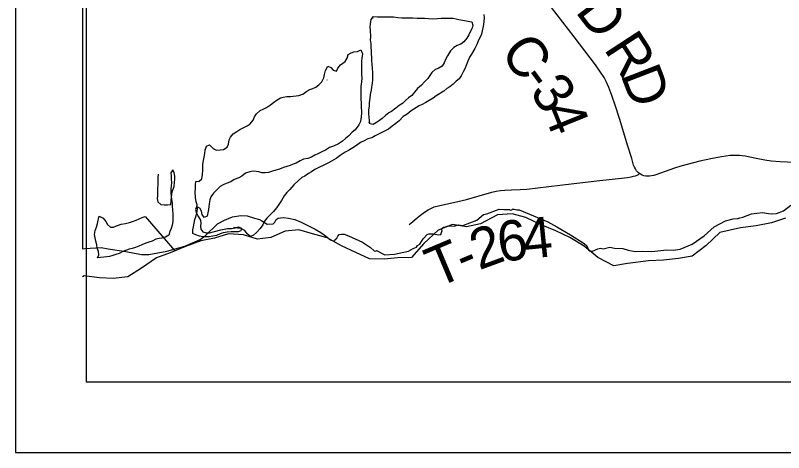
# Model space of a CAD drawing. Extents: x 63.4 to 97.4, y 0.4 to 22.4.
# Drawn here: x 65.412 to 66.497, y 14.42 to 15.037 of the extents above; entities that cross this region are included whole.
import ezdxf

# ---------------------------------------------------------------- set-up
doc = ezdxf.new("R2010")
doc.units = 0
for name, color, linetype in [('GM_X_County_Road', 7, 'Continuous'), ('GM_X_County_Road_Text', 7, 'Continuous'), ('GM_X_Major_Lake', 7, 'Continuous'), ('GM_X_Minor_River', 7, 'Continuous'), ('GM_X_Township_Road', 7, 'Continuous'), ('GM_X_Township_Road_Text', 7, 'Continuous'), ('SH_Cut_Line', 7, 'Continuous'), ('SH_Data', 7, 'Continuous')]:
    doc.layers.add(name, color=color, linetype=linetype)

msp = doc.modelspace()

# ---------------------------------------------------------------- linework, layer by layer
at = {"layer": 'GM_X_County_Road'}
for points in [[(65.5072, 16.9001), (65.5072, 14.7073), (65.5106, 14.7078), (65.5335, 14.7089), (65.5434, 14.707), (65.5685, 14.7035), (65.5904, 14.6991), (65.6006, 14.6993), (65.6261, 14.7038), (65.6518, 14.7108), (65.6733, 14.7202), (65.6803, 14.7255), (65.6978, 14.7425), (65.7075, 14.7478), (65.719, 14.7523), (65.7309, 14.7544), (65.7399, 14.7536), (65.75, 14.7507), (65.757, 14.7485), (65.7604, 14.7466), (65.7678, 14.7421), (65.7763, 14.7427), (65.7789, 14.7449), (65.7809, 14.7485), (65.7834, 14.7503), (65.7868, 14.751), (65.7909, 14.7514), (65.7983, 14.7507), (65.8072, 14.7484), (65.8161, 14.745), (65.8357, 14.7348), (65.8436, 14.7301), (65.8486, 14.7268), (65.8573, 14.7199), (65.8609, 14.7183), (65.8636, 14.7187), (65.8641, 14.7206), (65.8665, 14.7224), (65.868, 14.7253), (65.8698, 14.7276), (65.8731, 14.7281), (65.8767, 14.7279), (65.8828, 14.7257), (65.9027, 14.7164), (65.914, 14.7092), (65.919, 14.7046), (65.9214, 14.7039), (65.9223, 14.7048), (65.9343, 14.6988), (65.9476, 14.6996), (65.9675, 14.7038), (65.974, 14.7077), (65.9787, 14.7096), (65.9803, 14.7119), (65.9834, 14.7137), (65.9885, 14.7215), (65.9939, 14.7275), (65.9965, 14.7285), (66.0026, 14.7284), (66.0099, 14.727), (66.0133, 14.7274), (66.0151, 14.7329), (66.0141, 14.7339), (66.0152, 14.7364), (66.0169, 14.7377), (66.0187, 14.7379), (66.0222, 14.7391), (66.0267, 14.7396), (66.0319, 14.7393), (66.0384, 14.7409), (66.0445, 14.7402), (66.0643, 14.7479), (66.0733, 14.7555), (66.078, 14.7566), (66.0956, 14.7631), (66.1023, 14.7627), (66.1101, 14.7626), (66.1111, 14.7618), (66.1135, 14.7621), (66.114, 14.7632), (66.1168, 14.7633), (66.1204, 14.7623), (66.1239, 14.7624), (66.1643, 14.7451), (66.1769, 14.7383), (66.1965, 14.7272), (66.2157, 14.7149), (66.2194, 14.7115), (66.222, 14.706), (66.2243, 14.704), (66.2276, 14.7037), (66.2348, 14.7074), (66.2388, 14.7081), (66.2425, 14.707), (66.2519, 14.7095), (66.2587, 14.7081), (66.2703, 14.7078), (66.2779, 14.7055), (66.2879, 14.7033), (66.2978, 14.704), (66.3113, 14.7033), (66.3326, 14.7057), (66.3414, 14.7052), (66.3515, 14.7066), (66.3684, 14.7137), (66.3852, 14.7254), (66.3994, 14.7384), (66.4155, 14.7467), (66.4263, 14.7497), (66.4326, 14.7498), (66.4356, 14.7508), (66.4398, 14.7521), (66.4519, 14.7567), (66.4597, 14.7576), (66.4675, 14.7584), (66.476, 14.7573), (66.4809, 14.7565), (66.4872, 14.7572), (66.4972, 14.761), (66.5076, 14.7689)], [(66.2938, 14.8133), (66.2925, 14.8144), (66.2912, 14.8157), (66.2898, 14.8175), (66.2882, 14.8199), (66.2868, 14.8226), (66.2856, 14.8255), (66.2829, 14.8345), (66.2774, 14.8523), (66.2656, 14.8909), (66.2601, 14.9087), (66.255, 14.9234), (66.2505, 14.935), (66.2467, 14.9434), (66.2438, 14.9488), (66.2389, 14.9567), (66.2318, 14.9668), (66.2017, 15.0065), (66.1617, 15.058), (66.1446, 15.0801)], [(66.5236, 14.8284), (66.4925, 14.83), (66.48, 14.8311), (66.4708, 14.8323), (66.4585, 14.8348), (66.4433, 14.838), (66.4387, 14.8386), (66.4351, 14.8391), (66.4321, 14.8391), (66.4285, 14.8391), (66.422, 14.8387), (66.4097, 14.837), (66.3944, 14.8343), (66.3793, 14.831), (66.3523, 14.824), (66.3434, 14.8212), (66.317, 14.8118), (66.3139, 14.8109), (66.3108, 14.8103), (66.3079, 14.8099), (66.305, 14.8098), (66.3026, 14.8099), (66.3001, 14.8103), (66.2975, 14.8111), (66.2951, 14.8124), (66.2938, 14.8133)]]:
    msp.add_lwpolyline(points, dxfattribs=at)
at = {"layer": 'GM_X_Major_Lake'}
for points in [[(66.5001, 14.7507), (66.4804, 14.7439), (66.4588, 14.7397), (66.4367, 14.7367), (66.4071, 14.7302), (66.3882, 14.7119), (66.3684, 14.6971), (66.3491, 14.6937), (66.3278, 14.6914), (66.3066, 14.6903), (66.277, 14.6865), (66.2576, 14.6834), (66.2349, 14.6952), (66.2159, 14.7112), (66.1954, 14.7233), (66.1757, 14.7328), (66.1552, 14.7412), (66.1335, 14.7514), (66.1142, 14.7564), (66.0933, 14.7552), (66.0694, 14.7423), (66.0493, 14.7381), (66.0296, 14.7415)], [(66.0296, 14.7415), (66.0095, 14.7336), (65.9894, 14.7149), (65.9719, 14.6948), (65.9522, 14.6944), (65.9332, 14.6925), (65.9123, 14.6932), (65.8933, 14.702), (65.8729, 14.7115), (65.8527, 14.7229), (65.8322, 14.7282), (65.8125, 14.7339), (65.7932, 14.732), (65.773, 14.7233), (65.7541, 14.721), (65.7343, 14.7271), (65.7135, 14.7286), (65.6934, 14.7225), (65.6744, 14.7183), (65.6528, 14.7107), (65.6308, 14.7016), (65.6118, 14.6943), (65.5905, 14.6799), (65.5712, 14.6677), (65.5503, 14.6654), (65.531, 14.6662), (65.5093, 14.6689), (65.5072, 14.6675)]]:
    msp.add_lwpolyline(points, dxfattribs=at)
at = {"layer": 'GM_X_Minor_River'}
for points in [[(65.9128, 14.8838), (65.912, 14.8929), (65.9116, 14.8978), (65.9116, 14.9031), (65.9123, 14.9088), (65.9126, 14.9134), (65.9134, 14.9199), (65.9141, 14.9248), (65.9152, 14.9309), (65.916, 14.9355), (65.9167, 14.9412), (65.9174, 14.9457), (65.9174, 14.956), (65.9166, 14.9617), (65.9162, 14.9678), (65.9158, 14.9723), (65.9157, 14.9773), (65.9153, 14.9822), (65.9153, 14.9864), (65.9149, 14.9917), (65.9149, 14.9967), (65.9141, 15.002), (65.9145, 15.0062), (65.914, 15.0157), (65.9136, 15.0202), (65.914, 15.0248), (65.9147, 15.0309), (65.9181, 15.0351), (65.9238, 15.0347), (65.9299, 15.0347), (65.9352, 15.0344), (65.9409, 15.0348), (65.9466, 15.0344), (65.9527, 15.0337), (65.958, 15.0333), (65.9622, 15.033), (65.9739, 15.033), (65.9796, 15.0327), (65.9903, 15.0327), (65.9956, 15.0324), (66.0013, 15.032), (66.0085, 15.0321), (66.0138, 15.0325), (66.0187, 15.0329), (66.0237, 15.0325), (66.0305, 15.0325), (66.0347, 15.0318), (66.0389, 15.0307), (66.0571, 15.0277), (66.0586, 15.0228), (66.0575, 15.0186), (66.0549, 15.0136), (66.0526, 15.0091), (66.05, 15.0045), (66.0459, 14.9992), (66.0413, 14.9961), (66.0364, 14.9942), (66.0315, 14.9911), (66.0269, 14.9865), (66.0228, 14.9797), (66.0205, 14.9755), (66.0179, 14.9698), (66.0153, 14.9652), (66.0096, 14.9617), (66.0054, 14.9602), (66.0005, 14.956), (65.9949, 14.9476), (65.99, 14.943), (65.9858, 14.9384), (65.9801, 14.9335), (65.976, 14.9281), (65.9722, 14.9236), (65.9677, 14.9201), (65.9635, 14.9167), (65.959, 14.9125), (65.9544, 14.9094), (65.9495, 14.9056), (65.9438, 14.901), (65.9397, 14.8991), (65.9351, 14.8956), (65.9306, 14.8911), (65.9264, 14.8884), (65.9223, 14.8853), (65.9177, 14.8826), (65.9128, 14.8838), (65.9119, 14.8858)], [(65.9173, 15.0323), (65.917, 15.0337)], [(66.0738, 15.0381), (66.0745, 15.0331), (66.0738, 15.0278), (66.0734, 15.0236), (66.0727, 15.0191), (66.0716, 15.0149), (66.0705, 15.0099), (66.0686, 15.0057), (66.066, 15.0008), (66.0645, 14.9966), (66.0611, 14.9897), (66.0566, 14.9821), (66.0539, 14.9779), (66.0506, 14.9695), (66.0476, 14.9623), (66.0449, 14.957), (66.0419, 14.9513), (66.0393, 14.9471), (66.0351, 14.9436), (66.0306, 14.9394), (66.0261, 14.936), (66.0219, 14.9337)], [(65.8129, 14.9234), (65.8143, 14.924), (65.8184, 14.9255), (65.8241, 14.9297), (65.8283, 14.932), (65.8324, 14.9336), (65.8366, 14.9355), (65.8411, 14.9385), (65.8453, 14.9431), (65.8479, 14.9484), (65.849, 14.9534), (65.8505, 14.9587), (65.8535, 14.9652), (65.8577, 14.9633), (65.8612, 14.9592), (65.8657, 14.958), (65.868, 14.9622), (65.8714, 14.9668), (65.8782, 14.9714), (65.8808, 14.9763), (65.8823, 14.9813), (65.8865, 14.984), (65.8906, 14.9851), (65.8956, 14.9859), (65.9001, 14.9878), (65.9024, 14.9825), (65.9017, 14.9764), (65.901, 14.9723), (65.901, 14.9628), (65.901, 14.9582), (65.9014, 14.9533), (65.9015, 14.9479), (65.9011, 14.943), (65.9004, 14.9361), (65.9004, 14.9266), (65.9001, 14.9225), (65.9001, 14.9179), (65.9005, 14.9137), (65.9009, 14.9092), (65.901, 14.8989), (65.9006, 14.8936), (65.8999, 14.8871), (65.8976, 14.8822), (65.8923, 14.8753), (65.8882, 14.8719), (65.8833, 14.8669), (65.8787, 14.8627), (65.8742, 14.8592), (65.8685, 14.8554), (65.8617, 14.8523), (65.856, 14.8504), (65.8503, 14.8466), (65.8454, 14.8443), (65.8397, 14.8412), (65.8352, 14.8393), (65.8307, 14.8366), (65.8253, 14.8347), (65.8193, 14.8339), (65.8144, 14.8312), (65.8091, 14.8282), (65.8045, 14.8266), (65.8003, 14.8247), (65.7958, 14.8235), (65.7912, 14.822), (65.7856, 14.8197), (65.7803, 14.8181), (65.7757, 14.8166), (65.77, 14.815), (65.7651, 14.8143), (65.7605, 14.8146), (65.7563, 14.8157), (65.7522, 14.8165), (65.748, 14.8168), (65.7434, 14.8157), (65.7374, 14.8138), (65.7321, 14.8099), (65.7279, 14.8076), (65.7215, 14.8049), (65.7166, 14.8019), (65.7101, 14.7996), (65.7059, 14.7973), (65.7014, 14.7953), (65.692, 14.7858), (65.6886, 14.7805), (65.6871, 14.7763), (65.686, 14.7709), (65.6856, 14.7668), (65.6849, 14.7626), (65.6841, 14.758), (65.683, 14.7534), (65.6788, 14.7515), (65.6762, 14.7557), (65.675, 14.7602), (65.6727, 14.7648), (65.6681, 14.7667), (65.6666, 14.7625), (65.6682, 14.7576), (65.6709, 14.7526), (65.6739, 14.7477), (65.6743, 14.7435), (65.674, 14.7393)], [(65.8523, 14.9458), (65.8525, 14.9458)], [(66.0219, 14.9337), (66.0174, 14.9299), (66.0068, 14.923), (66.0026, 14.9199), (65.9969, 14.9165), (65.992, 14.9138), (65.9867, 14.9111), (65.9825, 14.9088), (65.9712, 14.9019), (65.9659, 14.8973), (65.9602, 14.8939), (65.9545, 14.8877), (65.9496, 14.8843), (65.9443, 14.8801), (65.9394, 14.8763), (65.9205, 14.8667), (65.9156, 14.864), (65.9103, 14.8625), (65.905, 14.8594), (65.8996, 14.8571), (65.8928, 14.8521), (65.883, 14.846), (65.8781, 14.8437), (65.8709, 14.8391), (65.8652, 14.8349), (65.8588, 14.8307), (65.8535, 14.828), (65.8478, 14.8253), (65.841, 14.8218), (65.8353, 14.8192), (65.8304, 14.8157), (65.8262, 14.8134), (65.8213, 14.8096), (65.8168, 14.8077), (65.8122, 14.8038), (65.8058, 14.7977), (65.8001, 14.7909), (65.7956, 14.7867), (65.7918, 14.7821), (65.7884, 14.7756), (65.7843, 14.7699), (65.7813, 14.7653), (65.7768, 14.76), (65.7722, 14.7554), (65.7677, 14.7504), (65.7639, 14.7458), (65.7617, 14.7409), (65.7579, 14.7359), (65.753, 14.7302), (65.7488, 14.7264), (65.7443, 14.7245), (65.7397, 14.7286), (65.7366, 14.7332), (65.7309, 14.7358), (65.726, 14.7365), (65.7203, 14.7373)], [(65.674, 14.7393), (65.6744, 14.7352), (65.677, 14.731), (65.6816, 14.7299), (65.6865, 14.7299), (65.6934, 14.7318), (65.7025, 14.7342), (65.707, 14.7349), (65.712, 14.7357), (65.7176, 14.7361), (65.7226, 14.7369), (65.7275, 14.7381), (65.7317, 14.7366), (65.731, 14.7324), (65.7268, 14.7312), (65.7211, 14.7312), (65.7169, 14.7312), (65.7116, 14.7308), (65.7059, 14.7296), (65.7014, 14.7284), (65.6964, 14.7261), (65.6911, 14.725), (65.6862, 14.7242), (65.6771, 14.7242), (65.6725, 14.7249), (65.6672, 14.7268), (65.663, 14.729), (65.663, 14.734), (65.6641, 14.7382), (65.6648, 14.7435), (65.666, 14.7484), (65.6678, 14.7538), (65.6689, 14.7598), (65.6697, 14.7644), (65.6693, 14.7693), (65.6677, 14.7735), (65.6666, 14.7796), (65.6665, 14.7876), (65.6669, 14.7921), (65.6668, 14.7975), (65.6672, 14.8024), (65.6717, 14.8028), (65.6759, 14.8062), (65.6766, 14.8123), (65.677, 14.818), (65.677, 14.8222), (65.6773, 14.8268), (65.6781, 14.8321), (65.6792, 14.8367), (65.6799, 14.8416), (65.6803, 14.8466), (65.6821, 14.8519), (65.6863, 14.8542), (65.6916, 14.8489), (65.6966, 14.8466), (65.7015, 14.8467), (65.7064, 14.8474), (65.7114, 14.8505), (65.7132, 14.8547), (65.7144, 14.8608), (65.7162, 14.865), (65.72, 14.8695), (65.7253, 14.873), (65.7295, 14.8757), (65.7348, 14.8784), (65.7397, 14.8807), (65.7439, 14.8837), (65.748, 14.8887), (65.7503, 14.8933), (65.7529, 14.8978), (65.7582, 14.9024), (65.7623, 14.9043), (65.7669, 14.9066), (65.7726, 14.9105), (65.7771, 14.9135), (65.782, 14.9174), (65.7866, 14.9204), (65.7907, 14.9212), (65.7957, 14.922), (65.801, 14.9224), (65.8129, 14.9234)], [(65.614, 14.8128), (65.6136, 14.8082), (65.6133, 14.8041), (65.6133, 14.798), (65.613, 14.7923), (65.613, 14.7824), (65.6126, 14.7782), (65.6134, 14.7736), (65.6176, 14.7699), (65.6226, 14.7695), (65.6271, 14.7695), (65.6317, 14.7699), (65.6324, 14.7753), (65.6328, 14.7798), (65.6331, 14.7848), (65.6342, 14.7893), (65.6365, 14.7954), (65.6372, 14.8007), (65.6376, 14.8053), (65.6375, 14.8099), (65.6368, 14.8144), (65.6348, 14.8186), (65.6318, 14.8144), (65.6322, 14.8098), (65.6326, 14.8057), (65.633, 14.8007), (65.6323, 14.7962), (65.6319, 14.7912), (65.632, 14.7863), (65.6324, 14.7813), (65.6328, 14.7768), (65.6339, 14.7715), (65.634, 14.7669), (65.6344, 14.7627), (65.6348, 14.7551), (65.6348, 14.7506), (65.6345, 14.746), (65.6337, 14.7407), (65.6326, 14.7361), (65.6307, 14.7315), (65.6292, 14.7266), (65.6243, 14.7235), (65.6194, 14.7224), (65.6152, 14.722), (65.6107, 14.7208), (65.6057, 14.7181), (65.6008, 14.7166), (65.5966, 14.715), (65.591, 14.7127), (65.5868, 14.7108), (65.5819, 14.7093), (65.5773, 14.7077), (65.5731, 14.7066), (65.564, 14.7035), (65.5591, 14.7008), (65.5542, 14.6992), (65.55, 14.6977), (65.5455, 14.6965), (65.5413, 14.6961), (65.5371, 14.6954), (65.5326, 14.695), (65.5284, 14.6946), (65.5303, 14.6988), (65.5295, 14.7033), (65.528, 14.7082), (65.5272, 14.7128), (65.526, 14.7181), (65.5248, 14.7227), (65.5241, 14.7276), (65.5248, 14.7333), (65.5267, 14.7379), (65.5285, 14.7428), (65.5293, 14.7478), (65.5308, 14.7531), (65.5365, 14.7505), (65.5403, 14.7459), (65.5426, 14.7414), (65.5468, 14.738), (65.551, 14.738), (65.5551, 14.7395), (65.5616, 14.7419), (65.568, 14.743), (65.5737, 14.7442), (65.5779, 14.7457), (65.5828, 14.7477), (65.587, 14.7496), (65.5915, 14.7515), (65.5957, 14.753), (65.6374, 14.7043)]]:
    msp.add_lwpolyline(points, dxfattribs=at)
at = {"layer": 'GM_X_Township_Road'}
msp.add_lwpolyline([(65.9683, 14.7416), (65.9707, 14.7435), (65.9828, 14.7533), (65.9903, 14.759), (65.9955, 14.7623), (66.001, 14.7652), (66.0039, 14.7664), (66.0099, 14.7681), (66.0372, 14.7741), (66.0494, 14.777), (66.0674, 14.7818), (66.0853, 14.7874), (66.0913, 14.7887), (66.0975, 14.7897), (66.1037, 14.7901), (66.113, 14.7904), (66.1255, 14.7909), (66.1348, 14.7916), (66.1812, 14.797), (66.2338, 14.8031), (66.2771, 14.8081), (66.2821, 14.8089), (66.2855, 14.8096), (66.2881, 14.8104), (66.2907, 14.8113), (66.2926, 14.8123), (66.2938, 14.8133)], dxfattribs=at)
at = {"layer": 'SH_Cut_Line'}
msp.add_lwpolyline([(65.5072, 16.9001), (65.5072, 14.7073), (65.5106, 14.7078), (65.5335, 14.7089), (65.5434, 14.707), (65.5685, 14.7035), (65.5904, 14.6991), (65.6006, 14.6993), (65.6261, 14.7038), (65.6518, 14.7108), (65.6733, 14.7202), (65.6803, 14.7255), (65.6978, 14.7425), (65.7075, 14.7478), (65.719, 14.7523), (65.7309, 14.7544), (65.7399, 14.7536), (65.75, 14.7507), (65.757, 14.7485), (65.7604, 14.7466), (65.7678, 14.7421), (65.7763, 14.7427), (65.7789, 14.7449), (65.7809, 14.7485), (65.7834, 14.7503), (65.7868, 14.751), (65.7909, 14.7514), (65.7983, 14.7507), (65.8072, 14.7484), (65.8161, 14.745), (65.8357, 14.7348), (65.8436, 14.7301), (65.8486, 14.7268), (65.8573, 14.7199), (65.8609, 14.7183), (65.8636, 14.7187), (65.8641, 14.7206), (65.8665, 14.7224), (65.868, 14.7253), (65.8698, 14.7276), (65.8731, 14.7281), (65.8767, 14.7279), (65.8828, 14.7257), (65.9027, 14.7164), (65.914, 14.7092), (65.919, 14.7046), (65.9214, 14.7039), (65.9223, 14.7048), (65.9343, 14.6988), (65.9476, 14.6996), (65.9675, 14.7038), (65.974, 14.7077), (65.9787, 14.7096), (65.9803, 14.7119), (65.9834, 14.7137), (65.9885, 14.7215), (65.9939, 14.7275), (65.9965, 14.7285), (66.0026, 14.7284), (66.0099, 14.727), (66.0133, 14.7274), (66.0151, 14.7329), (66.0141, 14.7339), (66.0152, 14.7364), (66.0169, 14.7377), (66.0187, 14.7379), (66.0222, 14.7391), (66.0267, 14.7396), (66.0319, 14.7393), (66.0384, 14.7409), (66.0445, 14.7402), (66.0643, 14.7479), (66.0733, 14.7555), (66.078, 14.7566), (66.0956, 14.7631), (66.1023, 14.7627), (66.1101, 14.7626), (66.1111, 14.7618), (66.1135, 14.7621), (66.114, 14.7632), (66.1168, 14.7633), (66.1204, 14.7623), (66.1239, 14.7624), (66.1643, 14.7451), (66.1769, 14.7383), (66.1965, 14.7272), (66.2157, 14.7149), (66.2194, 14.7115), (66.222, 14.706), (66.2243, 14.704), (66.2276, 14.7037), (66.2348, 14.7074), (66.2388, 14.7081), (66.2425, 14.707), (66.2519, 14.7095), (66.2587, 14.7081), (66.2703, 14.7078), (66.2779, 14.7055), (66.2879, 14.7033), (66.2978, 14.704), (66.3113, 14.7033), (66.3326, 14.7057), (66.3414, 14.7052), (66.3515, 14.7066), (66.3684, 14.7137), (66.3852, 14.7254), (66.3994, 14.7384), (66.4155, 14.7467), (66.4263, 14.7497), (66.4326, 14.7498), (66.4356, 14.7508), (66.4398, 14.7521), (66.4519, 14.7567), (66.4597, 14.7576), (66.4675, 14.7584), (66.476, 14.7573), (66.4809, 14.7565), (66.4872, 14.7572), (66.4972, 14.761), (66.5076, 14.7689)], dxfattribs=at)
at = {"layer": 'SH_Data'}
for p, q in [((65.4123, 21.4197), (65.4123, 14.4197)), ((65.5123, 21.3197), (65.5123, 14.5197)), ((65.5123, 14.5197), (72.3123, 14.5197)), ((65.5123, 14.5197), (65.5123, 14.5197)), ((65.4123, 14.4197), (72.4123, 14.4197))]:
    msp.add_line(p, q, dxfattribs=at)

# ---------------------------------------------------------------- texts
at = {"layer": 'GM_X_County_Road_Text'}
for s, rotation, p in [('D', 307.5919, (66.2021, 15.0421)), ('R', 303.0871, (66.2425, 14.9895)), ('C', 306.8644, (66.0956, 14.984)), ('D', 291.06, (66.2666, 14.9532)), ('-', 306.8114, (66.1236, 14.9467)), ('3', 305.753, (66.1374, 14.9282)), ('4', 291.9976, (66.1562, 14.903))]:
    msp.add_text(s, height=0.0568, rotation=rotation, dxfattribs=at).set_placement(p)
at = {"layer": 'GM_X_Township_Road_Text'}
for s, rotation, p in [('6', 7.7886, (66.0969, 14.6881)), ('4', 5.7049, (66.1311, 14.6927)), ('2', 20.1541, (66.0672, 14.6768)), ('T', 22.879, (66.0072, 14.6516)), ('-', 22.5334, (66.0462, 14.6681))]:
    msp.add_text(s, height=0.0568, rotation=rotation, dxfattribs=at).set_placement(p)

doc.saveas('drawing.dxf')
